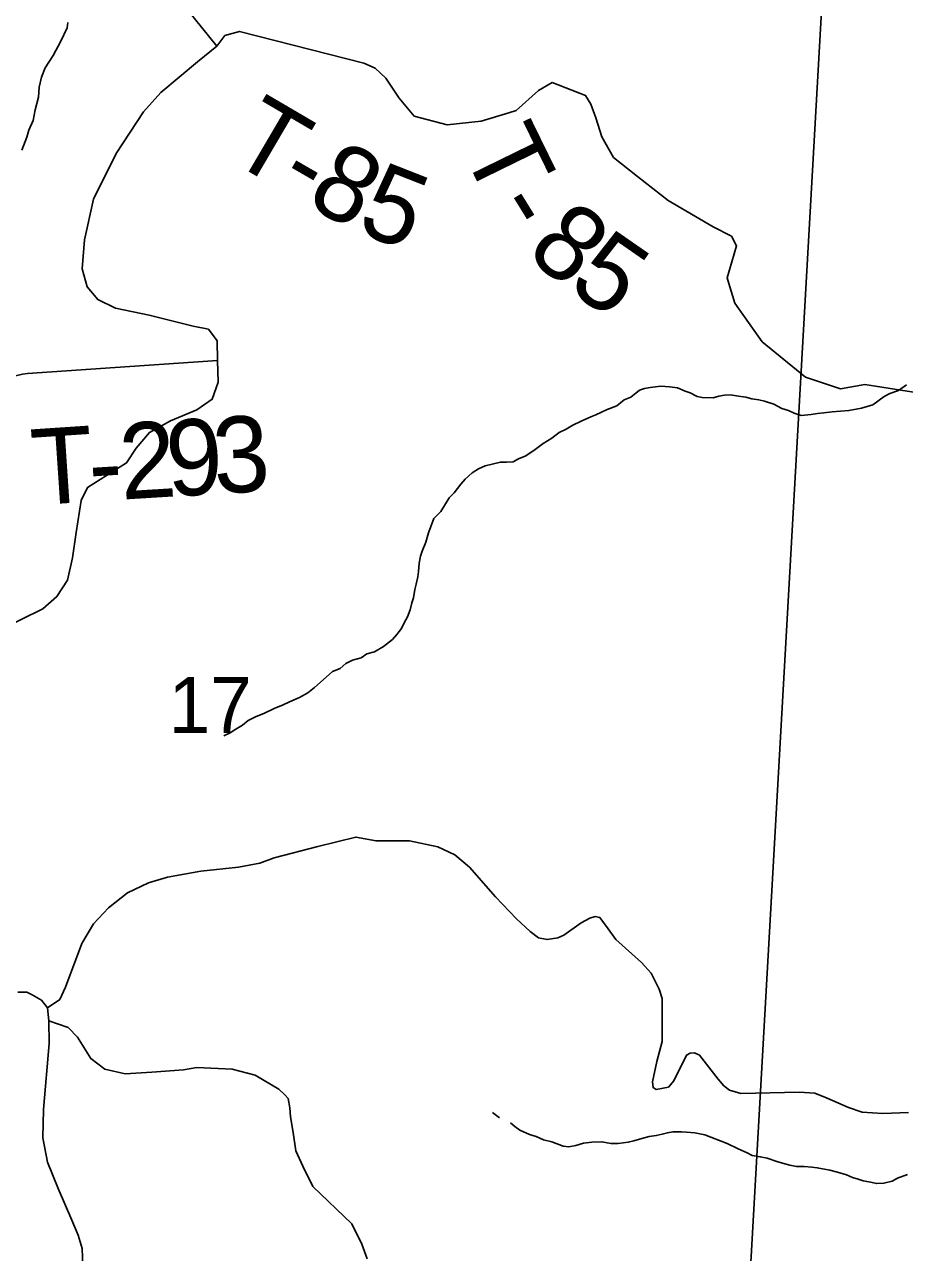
# Model space of a CAD drawing. Extents: x 0 to 34, y 0 to 22.
# Drawn here: x 4.174 to 4.831, y 18.127 to 19.045 of the extents above; entities that cross this region are included whole.
import ezdxf

# ---------------------------------------------------------------- set-up
doc = ezdxf.new("R2010")
doc.units = 0
for name, color, linetype in [('GM_X_County_Road', 7, 'Continuous'), ('GM_X_Minor_River', 7, 'Continuous'), ('GM_X_Section', 7, 'Continuous'), ('GM_X_Section_Text', 7, 'Continuous'), ('GM_X_Township_Road', 7, 'Continuous'), ('GM_X_Township_Road_Text', 7, 'Continuous'), ('GM_X_Township_ROW', 7, 'Continuous')]:
    doc.layers.add(name, color=color, linetype=linetype)

msp = doc.modelspace()

# ---------------------------------------------------------------- linework, layer by layer
at = {"layer": 'GM_X_County_Road'}
for points in [[(4.15466, 18.59221), (4.18723, 18.60822), (4.19781, 18.61735), (4.20574, 18.62951), (4.2095, 18.64621), (4.2121, 18.66519), (4.21583, 18.6891), (4.22074, 18.69898), (4.23474, 18.70773), (4.24988, 18.71725), (4.25706, 18.72827), (4.26688, 18.74005), (4.28279, 18.74882), (4.30248, 18.75683), (4.31383, 18.76482), (4.31835, 18.77773), (4.31794, 18.79374), (4.31751, 18.80846), (4.31105, 18.81717), (4.29967, 18.81942), (4.26667, 18.8277), (4.24164, 18.83295), (4.22836, 18.83937), (4.22038, 18.84884), (4.21655, 18.86249), (4.2184, 18.88412), (4.22515, 18.91449), (4.24212, 18.94867), (4.26252, 18.97982), (4.27537, 18.99427), (4.30299, 19.01709), (4.31737, 19.02889), (4.29531, 19.05615)], [(4.21745, 18.11019), (4.21677, 18.1297), (4.21368, 18.13962), (4.20889, 18.15091), (4.19863, 18.17452), (4.19072, 18.19429), (4.18715, 18.21263), (4.18766, 18.23377), (4.19199, 18.28317), (4.19174, 18.29998), (4.19072, 18.30966), (4.18614, 18.31552), (4.17927, 18.31934), (4.17519, 18.32138), (4.16857, 18.32138)]]:
    msp.add_lwpolyline(points, dxfattribs=at)
at = {"layer": 'GM_X_Minor_River'}
for points in [[(4.2059, 19.04653), (4.20546, 19.04274), (4.20073, 19.03256), (4.19486, 19.02203), (4.18902, 19.01264), (4.18625, 19.00585), (4.1846, 18.99828), (4.18408, 18.9907), (4.18164, 18.98125), (4.17999, 18.9733), (4.17683, 18.96614), (4.17522, 18.96085), (4.17164, 18.95104)], [(4.83295, 18.77575), (4.82681, 18.7713), (4.82033, 18.76912), (4.81613, 18.76692), (4.80768, 18.76061), (4.7993, 18.75809), (4.7898, 18.75635), (4.77729, 18.75542), (4.77122, 18.75477), (4.76628, 18.75409), (4.76172, 18.75341), (4.75413, 18.75278), (4.74886, 18.75439), (4.74473, 18.75636), (4.73983, 18.75796), (4.73383, 18.7611), (4.72667, 18.7635), (4.72252, 18.76433), (4.71723, 18.76518), (4.71271, 18.76639), (4.70742, 18.76724), (4.70137, 18.7681), (4.69682, 18.7678), (4.69264, 18.76711), (4.68846, 18.76605), (4.68013, 18.76619), (4.67635, 18.76701), (4.6711, 18.76976), (4.66733, 18.77096), (4.66169, 18.77334), (4.65565, 18.7742), (4.64922, 18.77469), (4.64124, 18.77368), (4.63706, 18.77299), (4.63325, 18.77154), (4.62672, 18.76633), (4.62176, 18.76452), (4.61638, 18.76005), (4.60913, 18.75714), (4.60073, 18.7531), (4.59691, 18.75165), (4.58966, 18.74836), (4.58355, 18.74542), (4.57857, 18.74247), (4.57322, 18.7399), (4.56785, 18.73581), (4.56134, 18.73175), (4.55519, 18.7273), (4.54829, 18.72248), (4.54295, 18.72029), (4.53875, 18.71808), (4.53382, 18.71778), (4.52927, 18.71786), (4.51786, 18.71502), (4.5129, 18.71283), (4.5083, 18.70986), (4.50291, 18.70502), (4.49981, 18.70127), (4.49478, 18.69491), (4.49092, 18.69117), (4.48468, 18.68102), (4.47967, 18.67579), (4.47729, 18.66976), (4.47569, 18.66485), (4.47367, 18.65805), (4.4709, 18.65126), (4.4697, 18.64748), (4.46847, 18.64219), (4.46798, 18.63612), (4.46753, 18.63195), (4.4663, 18.62665), (4.46547, 18.62249), (4.46423, 18.61643), (4.46302, 18.61266), (4.46179, 18.60736), (4.45981, 18.60208), (4.45746, 18.59756), (4.45549, 18.59342), (4.452, 18.58892), (4.44853, 18.58518), (4.44199, 18.57997), (4.43511, 18.57591), (4.4294, 18.57449), (4.42518, 18.57152), (4.41871, 18.56974), (4.41374, 18.56716), (4.40951, 18.56344), (4.40379, 18.56126), (4.39455, 18.55306), (4.39032, 18.54933)], [(4.39032, 18.54933), (4.38532, 18.54524), (4.3792, 18.54193), (4.37157, 18.53864), (4.36698, 18.53644), (4.36011, 18.53352), (4.35247, 18.52985), (4.34675, 18.52767), (4.34064, 18.52474), (4.33641, 18.52101), (4.33143, 18.51806), (4.32722, 18.51547), (4.32264, 18.51327)], [(4.52336, 18.23145), (4.5286, 18.22756)], [(4.5976, 18.20929), (4.59152, 18.20863), (4.58581, 18.20683), (4.58049, 18.20578), (4.57633, 18.20623), (4.56767, 18.20942), (4.56164, 18.21104), (4.556, 18.21342), (4.55111, 18.21502), (4.54396, 18.21818), (4.54022, 18.2209), (4.53698, 18.2236)], [(4.83354, 18.18514), (4.82629, 18.18222), (4.82209, 18.18002), (4.816, 18.1786), (4.81069, 18.17831), (4.80465, 18.17955), (4.8005, 18.18038), (4.79674, 18.18159), (4.79259, 18.1828), (4.78808, 18.18477), (4.7813, 18.18679), (4.77564, 18.1884), (4.7662, 18.19008), (4.76204, 18.19053), (4.75637, 18.19101), (4.75069, 18.19111), (4.74578, 18.19195), (4.74013, 18.19357), (4.73598, 18.19477), (4.72883, 18.19718), (4.72354, 18.19841), (4.7175, 18.19927), (4.71375, 18.20123), (4.70698, 18.20438), (4.69872, 18.20833), (4.68216, 18.21468), (4.67462, 18.21633), (4.66856, 18.21682), (4.66478, 18.21688), (4.65834, 18.21699), (4.65416, 18.2163), (4.65035, 18.21523), (4.64579, 18.21416), (4.64047, 18.21349), (4.63515, 18.21207), (4.62905, 18.21027), (4.62487, 18.2092), (4.61727, 18.20819), (4.61197, 18.20828), (4.60518, 18.20954), (4.5976, 18.20929)]]:
    msp.add_lwpolyline(points, dxfattribs=at)
at = {"layer": 'GM_X_Section'}
for points in [[(3.68636, 19.1354), (4.77041, 19.07293), (4.71243, 18.04874), (3.62875, 18.10856)], [(5.84575, 19.01008), (5.78398, 17.98891), (4.71243, 18.04874), (4.77041, 19.07293)]]:
    msp.add_lwpolyline(points, close=True, dxfattribs=at)
at = {"layer": 'GM_X_Township_Road'}
for points in [[(4.53569, 18.97916), (4.51499, 18.9728), (4.4896, 18.97009), (4.46495, 18.97648), (4.45354, 18.99011), (4.44365, 19.00489), (4.43567, 19.01246), (4.42732, 19.01624), (4.33439, 19.03993), (4.32341, 19.03687), (4.31737, 19.02889)], [(4.7, 18.85148), (4.69875, 18.8556), (4.70589, 18.87953), (4.70208, 18.88673), (4.68842, 18.8939), (4.65463, 18.91355), (4.63185, 18.93134), (4.61399, 18.94571), (4.60524, 18.96124), (4.60065, 18.97527), (4.59684, 18.98551), (4.59303, 18.99195), (4.56799, 19.00176), (4.55777, 18.99566), (4.54113, 18.98083), (4.53569, 18.97916)], [(4.15168, 18.77254), (4.15449, 18.77522), (4.1576, 18.77769), (4.16252, 18.78061), (4.16674, 18.7823), (4.17194, 18.78354), (4.17573, 18.78404), (4.31794, 18.79374)], [(4.60995, 18.36878), (4.60375, 18.37726), (4.60009, 18.37806), (4.5963, 18.37689), (4.58974, 18.37332), (4.57675, 18.36399), (4.57229, 18.36196), (4.56417, 18.36074), (4.55768, 18.36196), (4.5516, 18.36683), (4.54146, 18.37617), (4.52563, 18.39281), (4.50614, 18.41495), (4.4952, 18.42406), (4.48262, 18.43015), (4.46144, 18.43456), (4.43638, 18.43462), (4.42136, 18.43746), (4.3929, 18.43027)], [(4.8345, 18.23141), (4.81532, 18.23081), (4.79985, 18.23169), (4.78943, 18.23507), (4.77366, 18.24212), (4.76446, 18.24589), (4.75272, 18.24659), (4.709, 18.24567), (4.70071, 18.2482), (4.69634, 18.25142), (4.69219, 18.25626), (4.67816, 18.27445), (4.67447, 18.27606), (4.67125, 18.27583), (4.66849, 18.27445), (4.65905, 18.25511), (4.65491, 18.25051), (4.6457, 18.24866), (4.6434, 18.25005), (4.64294, 18.25442), (4.64616, 18.26962), (4.65023, 18.28454), (4.65023, 18.31671), (4.6479, 18.32373), (4.64205, 18.33572), (4.63489, 18.34364), (4.61573, 18.36088), (4.60995, 18.36878)], [(4.42981, 18.12213), (4.42571, 18.13308), (4.41818, 18.14814), (4.38911, 18.1762), (4.38159, 18.19125), (4.37646, 18.20288), (4.37441, 18.21657), (4.37244, 18.22815), (4.37187, 18.23495), (4.37078, 18.24183), (4.36822, 18.24469), (4.36374, 18.24889), (4.3459, 18.25926), (4.3289, 18.26382), (4.30237, 18.26507), (4.29241, 18.26341), (4.2688, 18.26158), (4.24872, 18.2604), (4.23355, 18.26378), (4.22316, 18.27173), (4.21321, 18.2879), (4.20616, 18.29496), (4.19174, 18.29998)]]:
    msp.add_lwpolyline(points, dxfattribs=at)
at = {"layer": 'GM_X_Township_ROW'}
for points in [[(5.5279, 18.60642), (5.51467, 18.66389), (5.14992, 18.72113), (4.992, 18.74591), (4.80167, 18.77578), (4.78348, 18.77271), (4.7573, 18.78138), (4.72501, 18.80786), (4.70448, 18.83665), (4.7, 18.85148)], [(4.3929, 18.43027), (4.36028, 18.42203), (4.34955, 18.41799), (4.33361, 18.41497), (4.30527, 18.41192), (4.28039, 18.40736), (4.26629, 18.40321), (4.25053, 18.39575), (4.23643, 18.38455), (4.22524, 18.37252), (4.21643, 18.35778), (4.20421, 18.32519), (4.19988, 18.31603), (4.19072, 18.30966)]]:
    msp.add_lwpolyline(points, dxfattribs=at)

# ---------------------------------------------------------------- texts
at = {"layer": 'GM_X_Section_Text'}
msp.add_text('17', height=0.041856, rotation=0.00001, dxfattribs=at).set_placement((4.28121, 18.51527))
at = {"layer": 'GM_X_Township_Road_Text'}
for s, rotation, p in [('T', 329.61339, (4.3242, 18.94505)), ('T', 296.07249, (4.50012, 18.95179)), ('8', 331.24638, (4.38259, 18.91099)), ('-', 329.92566, (4.36115, 18.92338)), ('5', 338.52754, (4.42039, 18.89081)), ('-', 301.68822, (4.52173, 18.9083)), ('8', 320.28677, (4.54712, 18.87334)), ('5', 325.24461, (4.57831, 18.84773)), ('3', 3.50914, (4.31598, 18.69406)), ('T', 3.82013, (4.1805, 18.68549)), ('2', 3.52212, (4.24612, 18.68977)), ('9', 3.51108, (4.28105, 18.69192)), ('-', 3.55101, (4.22283, 18.68832))]:
    msp.add_text(s, height=0.05682, rotation=rotation, dxfattribs=at).set_placement(p)

doc.saveas('drawing.dxf')
